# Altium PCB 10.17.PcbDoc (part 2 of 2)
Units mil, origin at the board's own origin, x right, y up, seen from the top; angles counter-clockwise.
Board outline 3750 x 1920 mil, 2 copper layers (Top Layer, Bottom Layer), stack 30.359 mil thick; 119 components, 118 nets, 550 pads, 365 vias.
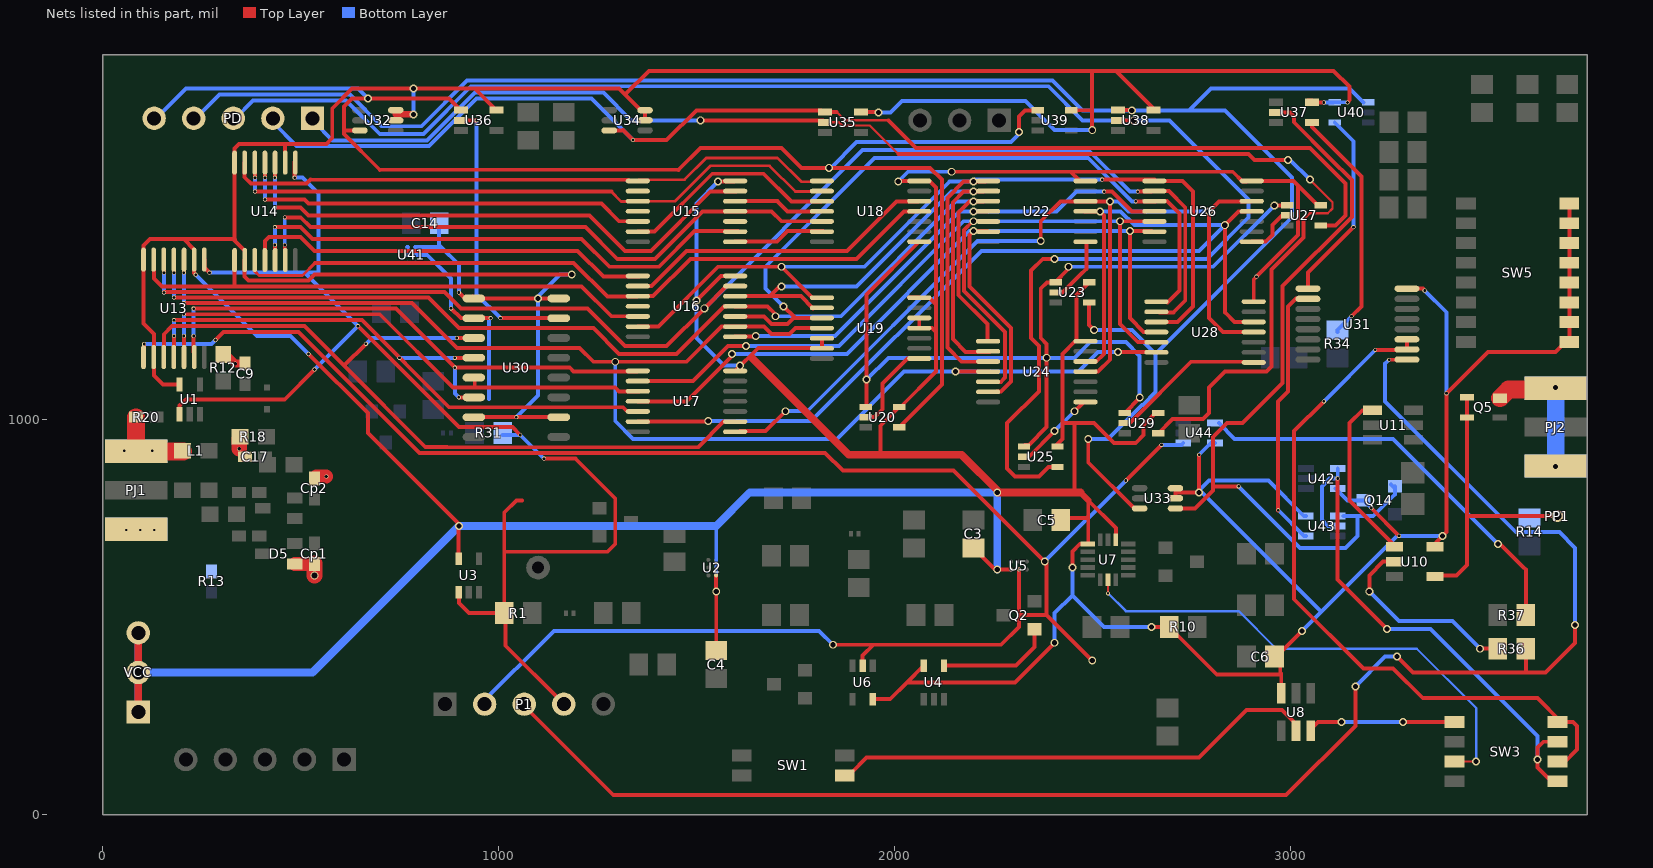
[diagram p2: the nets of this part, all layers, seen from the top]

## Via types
v1: diameter 20, hole 13, Top Layer to Bottom Layer, 179 vias
v2: diameter 10, hole 6.5, Top Layer to Bottom Layer, 137 vias
v3: diameter 10, hole 7, Top Layer to Bottom Layer, 28 vias
v4: diameter 10, hole 8, Top Layer to Bottom Layer, 10 vias
v5: diameter 10, hole 6, Top Layer to Bottom Layer, 7 vias
v6: diameter 8, hole 6, Top Layer to Bottom Layer, 2 vias
v7: diameter 20, hole 15, Top Layer to Bottom Layer, 1 vias
v8: diameter 10, hole 6.5, Top Layer to Bottom Layer, tented top, 1 vias

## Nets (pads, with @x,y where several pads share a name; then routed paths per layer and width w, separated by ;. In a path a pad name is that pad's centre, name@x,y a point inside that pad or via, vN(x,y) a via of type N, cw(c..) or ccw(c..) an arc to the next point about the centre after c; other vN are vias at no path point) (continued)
NetU10_1: U10.1 U11.1 | length 436.6
  Top Layer w10: U11.1@3208.43,1022.4 3182.4,1022.4 3150,990 3150,795 U10.1@3270,675
NetU19_8: U19.8 U20.2 | length 234.8
  Top Layer w10: U20.2@1927.68,1005 1950,1005 1970,1025 1970,1090 2033.23,1153.23 U19.8@2063.03,1153.23
NetU22_8: U22.8 U23.2 | length 167.2
  Top Layer w10: U23.2@2407.68,1320 2425,1320 2467.46,1362.46 2467.57,1362.46 2485,1379.89 U22.8@2485,1445
NetU24_8: U24.8 U25.2 | length 210.3
  Top Layer w10: U25.2@2327.68,905 2340,905 v1(2405,970) ; v1(2455,1020) U24.8@2475,1040
  Bottom Layer w10: v1(2405,970) v1(2455,1020) v1@2460,1025
NetU26_8: U26.8 U27.2 | length 119.3
  Top Layer w10: U26.8@2903.03,1448.23 2938.23,1448.23 2955,1465 2955,1490 U27.2@2980,1515
NetU28_8: U28.8 U29.2 | length 381.5
  Top Layer w10: U29.2@2582.68,990 2595,990 2750,1145 U28.8@2900,1145
NetU41_B2: U41.B2 U41.B3 | length 19.8
  Bottom Layer w10: U41.B2@770,1415 770.16,1415.16 U41.B3@770.16,1434.69
P1: U14.13 U15.1 U18.1 | length 1538
  Top Layer w7: U15.1@1330,1605 U15.1@1335,1600 ; U15.1@1351.97,1601.77 1355.2,1605 1470,1605 1525,1660 1705,1660 1765,1600 U18.1@1815,1600
  Top Layer w8: 525,1605 U15.1@1330,1605
  Top Layer w10: U14.13@358.82,1648.03 358.82,1611.18 375,1595 515,1595 525,1605
P1-: U15.2
P2: U14.12 U15.3 U18.2 | length 1557.3
  Top Layer w7: 1285,1575 1310,1550 U15.3@1350,1550 ; U15.3@1351.97,1550.59 1445.59,1550.59 1535,1640 1685,1640 1750,1575 U18.2@1810,1575
  Top Layer w10: v3(385,1575) 1285,1575 ; v3(385,1610) U14.12@385,1635
  Bottom Layer w10: v3(385,1575) v3(385,1610)
P2-: U15.4
P3: U14.11 U15.5 | length 1002.8
  Top Layer w10: v3(410,1555) 510,1555 520,1545 1260,1545 1305,1500 U15.5@1325,1500 ; v3(410,1610) U14.11@410,1620
  Bottom Layer w10: v3(410,1555) v3(410,1610)
P3-: U15.6 U18.3 | length 552.6
  Top Layer w10: U15.6@1351.97,1473.82 1393.82,1473.82 1540,1620 1670,1620 1740,1550 U18.3@1815,1550
P4: U14.10 U15.13 | length 1362.7
  Top Layer w10: v3(435,1535) 500,1535 520,1515 1230,1515 1320,1425 1385,1425 1535,1575 U15.13@1600,1575 ; v3(435,1610) U14.10@435,1625
  Bottom Layer w10: v3(435,1535) v3(435,1610)
P4-: U15.12 U18.4 | length 227.9
  Top Layer w10: U15.12@1598.03,1550.59 1705,1550.59 1705,1550 1730,1525 U18.4@1815,1525
P5: U14.6 U15.11 U18.5 | length 1561.8
  Top Layer w10: U14.6@460,1400 v3(460,1440) ; v3(460,1510) 500,1510 525,1485 1220,1485 1300,1405 1395,1405 1515,1525 U15.11@1598.03,1525 1690,1525 1715,1500 U18.5@1800,1500 ; U18.5@1816.97,1499.41 1824.41,1499.41 U18.5@1825,1500
  Bottom Layer w10: v3(460,1440) v3(460,1510)
P5-: U15.10
P6: U14.5 U15.9 | length 1328.7
  Top Layer w10: U14.5@435,1405 v3(435,1440) ; v3(435,1485) 500,1485 530,1455 1210,1455 1280,1385 1405,1385 1495,1475 U15.9@1605,1475
  Bottom Layer w10: v3(435,1440) v3(435,1485)
P6-: U15.8 U18.6 | length 236.6
  Top Layer w10: U15.8@1598.03,1448.23 1703.23,1448.23 1730,1475 1820,1475 1818.82,1473.82 U18.6@1816.97,1473.82
P7: U14.4 U16.1 | length 1038.6
  Top Layer w10: U14.4@410,1401.97 410,1450 420,1460 500,1460 535,1425 1200,1425 1265,1360 U16.1@1355,1360
P7-: U16.2 U18.12 | length 796.6
  Top Layer w10: U16.2@1351.97,1336.18 1386.18,1336.18 1475,1425 1880,1425 2005,1550 U18.12@2060,1550
P8: U14.3 U16.3 U18.11 | length 1843.7
  Top Layer w8: U14.3@384.41,1401.97 384.41,1373.59 395,1363 505,1363 537,1395
  Top Layer w10: 537,1395 585,1395 1190,1395 1275,1310 U16.3@1350,1310 ; U16.3@1351.97,1310.59 1390.59,1310.59 1485,1405 1905,1405 2025,1525 U18.11@2060,1525
P8-: U16.4
P9: U13.13 U14.1 U16.5 | length 1339.5
  Top Layer w10: U13.13@130,1395 130,1355 150,1335 1210,1335 1285,1260 U16.5@1325,1260 ; 333.23,1336.77 U14.1@333.23,1401.97
P9-: U16.6 U19.1 U22.1 U24.3 U26.1 U28.3 | length 2675.6
  Top Layer w10: U16.6@1351.97,1233.82 1403.82,1233.82 1555,1385 v1(1715,1385) U19.1@1790,1310 ; U24.3@2225,1145 2170,1145 2134,1181 2134,1559 2175,1600 U22.1@2230,1600 ; v2(2525,1605) 2656.97,1605 U26.1@2656.97,1601.77 2728.23,1601.77 2755,1575 2755,1285 2715,1245 U28.3@2660,1245
  Bottom Layer w10: v1(1715,1385) 1925,1385 2140,1600 v1(2200,1600) 2205,1605 v2(2525,1605)
P10: U13.12 U16.13 U26.2 U28.2 | length 3365.2
  Top Layer w10: v3@155,1321 864,1321 905,1280 1225,1280 1320,1185 1425,1185 v1(1520,1280) U16.13@1575,1335 ; v3(155,1370) U13.12@155,1400 ; v2(2615,1575) U26.2@2650,1575 ; U26.2@2656.97,1576.18 2693.82,1576.18 2735,1535 2735,1300 2705,1270 U28.2@2670,1270
  Bottom Layer w10: v3(155,1320) v3(155,1370) ; v1(1520,1280) 1920,1680 2490,1680 2595,1575 v2(2615,1575)
P10-: U16.12 U19.2 U22.2 U24.2 | length 1369.7
  Top Layer w10: U16.12@1598.03,1310.59 1685.59,1310.59 ; v1@1710,1335 1685.59,1310.59 ; v1@1713.82,1336.18 v1(1715,1335) ; U19.2@1795,1280 1764.41,1310.59 1685.59,1310.59 ; U22.2@2225,1575 2175,1575 2148,1548 2148,1202 2180,1170 U24.2@2240,1170
  Bottom Layer w10: v1(1715,1335) 1905,1335 2145,1575 v1(2200,1575)
P11: U13.11 U16.11 U22.3 U24.1 | length 2762.6
  Top Layer w10: v3(180,1307) 823,1307 900,1230 1240,1230 1305,1165 1450,1165 1570,1285 U16.11@1575,1285 ; v3(180,1370) U13.11@180,1408.03 ; U16.11@1598.03,1285 1680,1285 v1@1700,1265 ; v1@1699.41,1259.41 v1(1700,1260) ; U22.3@2225,1550 2190,1550 2162,1522 2162,1313 2235,1240 U24.1@2235,1200
  Bottom Layer w10: v3(180,1307) v3(180,1370) ; v1(1700,1260) 1865,1260 2155,1550 v1(2200,1550)
P11-: U16.10 U19.3 U26.3 U28.1 | length 1849.9
  Top Layer w10: U16.10@1598.03,1259.41 1670.59,1259.41 1690,1240 1730,1240 1747.5,1257.5 v1(1720,1285) ; 1745,1255 U19.3@1815,1255 ; v2(2610,1550) U26.3@2660,1550 ; U26.3@2656.97,1550.59 2689.41,1550.59 2720,1520 2720,1325 U28.1@2690,1295
  Bottom Layer w10: v1(1720,1285) 1675,1330 1675,1385 1950,1660 2490,1660 2600,1550 v2(2610,1550)
P12: U13.10 U16.9 U19.4 U24.4 U28.6 | length 3546.3
  Top Layer w10: v3(205,1293) 782,1293 895,1180 1205,1180 1240,1145 v1(1295,1145) 1475,1145 1563.82,1233.82 U16.9@1598.03,1233.82 1671.18,1233.82 1690,1215 1735,1215 1750,1230 U19.4@1815,1230 ; v3@205.59,1370.59 U13.10@205.59,1408.03 ; v1(2155,1120) U24.4@2236.97,1120 U24.4@2240,1120 ; v1(2565,1170) U28.6@2660,1170
  Bottom Layer w10: v3(205,1293) v3(205,1370) ; v1(1295,1145) 1295,995 1340,950 1855,950 2025,1120 v1(2155,1120) 2465,1120 2515,1170 v1(2565,1170)
P12-: U16.8 U22.4 U26.4 | length 1243.9
  Top Layer w10: U16.8@1598.03,1208.23 v1@1650,1208.23 ; v1(2200,1525) U22.4@2235,1525 ; v8(2530,1575) 2550,1575 2600,1525 U26.4@2635,1525
  Bottom Layer w10: v1(1650,1210) 1850,1210 2165,1525 v1(2200,1525) 2410,1525 2460,1575 v8(2530,1575)
P13: U13.6 U17.1 U30.6 | length 1411.7
  Top Layer w10: U13.6@230,1170 v3(230,1210) ; v3(230,1279) 741,1279 v2(890,1130) 1180,1130 1190,1120 U17.1@1350,1120 ; v2(900,1055) U30.6@937.72,1055
  Bottom Layer w10: v3(230,1210) v3(230,1279) ; v2(890,1130) 890,1065 v2(900,1055)
P13-: U17.2 U22.5 U24.5 U26.5 U28.5 | length 2365.5
  Top Layer w10: U17.2@1351.97,1096.18 1491.18,1096.18 1580,1185 v1@1620,1185 ; U24.5@2236.97,1094.41 2269.41,1094.41 2280,1105 2280,1220 2176,1324 2176,1477.87 2198.13,1500 U22.5@2240,1500 ; U28.5@2655,1195 2615,1195 2570,1240 v1(2570,1500) U26.5@2655,1500
  Bottom Layer w10: v1(1625,1185) 1860,1185 2175,1500 v1(2570,1500)
  other v1: 2200,1500
P14: U13.5 U17.3 U30.5 | length 1325.8
  Top Layer w10: 205,1190 v3(205,1210) ; v3(205,1265) 700,1265 885,1080 940,1080 ; U30.5@940,1100 940,1080 ; U17.3@1355,1070 1305,1070 1295,1080 940,1080
  Bottom Layer w10: v3(205,1210) v3(205,1265)
P14-: U17.4 U22.6 U24.6 U26.6 U28.4 | length 2276.6
  Top Layer w10: U17.4@1351.97,1045 1475,1045 1590,1160 v1(1590,1165) ; U22.6@2235,1475 v1(2200,1475) 2190,1465 2190,1335 2295,1230 2295,1095 2270,1070 U24.6@2260,1070 ; U28.4@2650,1220 2630,1220 2595,1255 v1(2595,1475) U26.6@2650,1475
  Bottom Layer w10: v1(1590,1165) 1880,1165 2190,1475 v1(2595,1475)
P15: U13.4 U17.5 U30.4 | length 1510.3
  Top Layer w10: U13.4@180,1175 v3(180,1210) ; v3(180,1250) 655,1250 875,1030 1315,1030 U17.5@1325,1020 ; v2(890,1155) U30.4@937.72,1155 U30.4@945,1155
  Bottom Layer w10: v3(180,1210) v3(180,1250) ; v2(750,1155) 800,1155 v2(890,1155)
P15-: U17.6 U22.11 U24.12 U26.11 U28.12 | length 2826.1
  Top Layer w10: U17.6@1351.97,993.82 1526.18,993.82 v1(1530,995) ; U22.11@2480,1525 U22.11@2483.03,1525 v1(2520,1525) 2530,1515 2530,1165 U24.12@2510,1145 ; U28.12@2900,1245 2860,1245 2835,1270 2835,1495 2840,1495 2870,1525 U26.11@2900,1525
  Bottom Layer w10: v1(1530,995) 1733.13,995 ; 1735,995 1790,995 2220,1425 2770,1425 v1(2835,1490) 2606.87,1490 2571.87,1525 v1(2520,1525)
P16: U13.3 U17.9 U30.3 | length 2004.1
  Top Layer w10: U13.3@154.41,1171.97 154.41,1214.41 175,1235 510,1235 610,1135 ; v2(665,1190) 610,1135 ; 870,929 1505,929 ; 870,930 815,930 610,1135 ; v2(895,1205) U30.3@937.72,1205 ; 1505,930 1568.82,993.82 U17.9@1598.03,993.82
  Bottom Layer w10: v2(665,1190) 680,1205 v2(895,1205)
P16-: U17.8 U22.12 U24.11 U26.12 U28.11 | length 2428.8
  Top Layer w10: U17.8@1610,970 1675,970 v1(1725,1020) v1@1727.64,1020 ; v1(2370,1450) 2370,1500 2420,1550 v1(2545,1550) 2545,1150 2515,1120 U24.11@2510,1120 ; U26.12@2900,1550 2820,1550 v1(2795,1525) 2795,1255 2830,1220 U28.11@2908.03,1220 U28.11@2910,1220
  Bottom Layer w10: v1(1725,1020) 1780,1020 2210,1450 v1@2369,1450 ; v1(2545,1550) 2566.67,1550 2591.67,1525 v1(2795,1525)
PD: U18.8 U20.1 U23.1 U25.1 U27.1 U29.1 | length 2521.8
  Top Layer w10: U20.1@1930,1030 v1(1930,1100) 1930,1315.2 U18.8@2063.03,1448.23 ; U25.1@2330,935 2340,935 2385,980 v1(2385,1155) 2385,1190 2370,1205 2370,1330 2385.59,1345.59 U23.1@2405.59,1345.59 ; U23.1@2407.68,1345.59 U23.1@2405.59,1345.59 ; v1(2440,1385) 2440,1380 U23.1@2405.59,1345.59 ; U29.1@2582.68,1015.59 v1@2620,1052.91 ; v1(2960,1540) U27.1@2995,1540
  Bottom Layer w10: v1(1930,1100) 1985,1155 2455,1155 2495,1195 2585,1195 2620,1160 v1(2620,1055) ; v1(2440,1385) 2805,1385 v1(2960,1540)
PD1: PD.5 U20.4 U32.3 U36.1 U39.1 | length 3893.5
  Top Layer w8: 700,1630 1455,1630
  Top Layer w10: U32.3@649.72,1729.41 614.41,1729.41 610,1725 ; 700,1630 610,1720 610,1725 ; U36.1@905,1780 875,1810 v1(670,1810) 630,1810 610,1790 610,1725 ; 1455,1630 1510,1685 1715,1685 1765,1635 2090,1635 2120,1605 2120,1087.09 U20.4@2012.32,979.41 ; v1(2315,1725) 2315,1765 2330,1780 U39.1@2365,1780
  Bottom Layer w10: PD.5@135,1760 210,1835 645,1835 v1(670,1810) ; v1(1835,1635) 1840,1635 1905,1700 2295,1700 2315,1720 v1(2315,1725)
PD2: PD.4 U23.4 U33.3 U38.1 U40.1 | length 4877.8
  Top Layer w10: v1(2490,950) 2490,890 U33.3@2605,775 ; U23.4@2492.32,1294.41 2492.32,1237.68 v1(2505,1225) ; U38.1@2564.72,1780.59 2599.41,1780.59 v1(2600,1780)
  Bottom Layer w10: PD.4@230,1755 295,1820 625,1820 705,1740 805,1740 920,1855 2400,1855 2475,1780 v1(2600,1780) 2745,1780 ; v1(2490,950) 2540,950 2626,1036 2627.87,1036 2660,1068.13 2660,1165 ; v1(2505,1225) 2600,1225 2660,1165 ; U40.1@3185,1800 3150,1835 2800,1835 2745,1780 ; 2660,1165 3005,1510 3005,1610 2835,1780 2745,1780
PD3: PD.3 U25.4 U38.2 | length 4177.8
  Top Layer w10: v1(2405,1405) 2375,1405 2345,1375 2345,1205 2365,1185 2365,1070 2285,990 2285,875 2305,855 2365,855 2389.41,879.41 U25.4@2412.32,879.41 ; U38.2@2564.72,1755 v1(2605,1755)
  Bottom Layer w10: PD.3@330,1755 PD.3@335,1760 ; PD.3@335,1750 PD.3@335,1760 ; v1(2405,1405) 2790,1405 2895,1510 2895,1555 2695,1755 v1(2605,1755) 2475,1755 2389,1841 931,1841 810,1720 700,1720 615,1805 380,1805 PD.3@335,1760
PD4: PD.2 U27.4 U34.3 U35.1 | length 3155.8
  Top Layer w6: 1854.41,1775.59 1875,1755 1985,1755
  Top Layer w10: U34.3@1279.72,1729.41 1315.59,1729.41 ; 1315,1730 1315.59,1729.41 ; U35.1@1820,1775 1815,1780 1500,1780 1425,1705 v4(1340,1705) 1315.59,1729.41 ; U35.1@1824.72,1775.59 1854.41,1775.59 ; 1985,1755 2055,1685 3050,1685 3140,1595 3140,1515 3114.41,1489.41 U27.4@3077.32,1489.41
  Bottom Layer w10: PD.2@430,1750 490,1690 825,1690 945,1810 1235,1810 v4(1340,1705)
PD5: PD.1 U29.4 U35.2 | length 3649.6
  Top Layer w6: U35.2@1825,1750 1860,1750 1868,1742 1938,1742 2010,1670 ; 3034,1504 3050,1520 3095,1520 3107,1532 3107,1548 v1(3050,1605)
  Top Layer w10: v1@1515,1755 1820,1755 U35.2@1825,1750 ; 2010,1670 2895,1670 2910,1655 v1(2995,1655) ; U29.4@2667.32,964.41 2702.91,1000 2780,1000 2795,1015 2795,1080 2835,1120 2940,1120 2953,1133 2953,1378.2 3034,1459.2 3034,1504
  Bottom Layer w10: PD.1@535,1750 581,1704 819.2,1704 940.2,1825 1265,1825 1335,1755 v1(1510,1755) ; v1(2995,1655) 3000,1655 v1(3050,1605)
PIE: P1.4 R1.1 R31.1 U1.1 U3.1 U13.8 U14.8 | length 3399.7
  Top Layer w10: U1.1@194.41,1012.6 194.41,1034.41 210,1050 460,1050 v4(535,1125) ; U13.8@256.77,1403.03 256.77,1383.23 v2(270,1370) ; v2(485,1610) U14.8@485,1650 ; v2(645,1235) 900,980 900,979.69 1035.32,979.69 v2(1055,960) ; U3.1@900,560 900,535 925,510 1014.41,510 1014.41,495.59 1017.5,492.5 1017.5,427.5 P1.4@1157.5,287.5 ; R1.1@1014.57,510 1014.57,665 ; 1060,795 1045,795 1014.57,764.57 1014.57,665 ; v2(1115,900) 1195,900 1295,800 1295,685 1275,665 1014.57,665
  Bottom Layer w10: v2(270,1370) 510,1370 ; v2(485,1610) 505,1610 545,1570 545,1370 510,1370 ; v4(535,1125) v2(645,1235) 510,1370 ; R31.1@1010,960 v2(1055,960) v2(1115,900)
PIE_Delayed: U30.2 U41.A2 | length 506
  Top Layer w10: v2(880,1280) 905,1255 U30.2@937.72,1255 v2(980,1255)
  Bottom Layer w10: U41.A2@789.84,1415 820,1415 880,1355 v2(880,1280) ; 976,1051 976,1251 v2(980,1255)
Q2_CONTROL: Q2.1 U4.4 | length 293.5
  Top Layer w10: U4.4@2125.59,377.32 2307.32,377.32 2354.37,424.37 Q2.1@2354.37,469.57
RCO: U30.15 U36.2 | length 707.1
  Top Layer w10: U36.2@910,1755 v2(945,1755) ; v2(1005,1255) U30.15@1152.28,1255
  Bottom Layer w10: v2(945,1755) 945,1315 v2(1005,1255)
RXGND: C9.2 C17.2 Cp1.2 Cp2.2 D5.1 L1.1 PJ1.2 R12.1 R13.2 R18.2 R20.2 | length 442.7
  Top Layer w8: v5(130,720) PJ1.2@147,703
  Top Layer w20: R12.1@305,1163.46 311.54,1163.46 v4@334.41,1140.59 ; v4(335,1140) v4@334.41,1140.59 ; C9.2@360,1140.59 v4@334.41,1140.59
  Top Layer w35: D5.1@485.35,634.41 Cp1.2@535,634.41 ; Cp2.2@540,855 v4(565,855)
  Top Layer w35.43: PJ1.2@70,918.43 PJ1.2@85,918.43
  Top Layer w40: PJ1.2@84.41,920.59 PJ1.2@85,920 ; v4(345,925) R18.2@345,950 ; v7(535,605) Cp1.2@535,634.41 Cp1.2@535,635
  Top Layer w45: PJ1.2@84.41,920.59 R20.2@84.41,1005 ; PJ1.2@85,918.43 L1.1@203.43,918.43
  Bottom Layer w40: PJ1.2@65,721.57 PJ1.2@70,721.57
  other v5: 60,720 95,720 55,920 125,920
SCLK: SW3.1 SW3.3 U42.4 U43.2 | length 1334.7
  Top Layer w10: 3120,595 3120,595.2 ; v2(3120,850) 3120,595.2 ; v1(3245,470) 3245,470.2 3120,595.2 ; SW3.1@3660,85 3625,120 3625,170 3640,185 SW3.3@3680,185
  Bottom Layer w10: U43.2@3105,730 3095,730 3080,745 3080,830 3100,850 v2(3120,850) 3120.28,850.28 U42.4@3120.28,875.59 ; v1(3245,470) 3355,470 3625,200 v1(3625,140)
SCLK_EN: R34.1 U37.4 | length 611.3
  Top Layer w10: U37.4@3055,1745 3055,1737.69 3180,1612.69 3180,1285 v2(3155,1260) ; 3055.28,1739.72 U37.4@3055.28,1749.41
  Bottom Layer w10: R34.1@3120,1220 3120,1225 v2(3155,1260)
SDATA: R37.1 U44.4 | length 1038.3
  Top Layer w10: v1@3530.2,685 3590.1,625.1 ; 3590,625 3595.43,619.57 R37.1@3595.43,505
  Bottom Layer w10: U44.4@2820,990 2860,950 3260,950 v1(3525,685)
SENSOROUT: SW3.2 SW3.4 U31.10 U31.11 | length 1763
  Top Layer w10: v2(3085,1045) 3010,970 3010,545 3185,370 3260,370 3335,295 3625,295 SW3.4@3685,235 ; v2(3215,1175) U31.10@3275,1175 ; U31.10@3295,1176.02 U31.11@3295,1200 ; SW3.2@3690,130 3725,165 3725,225 3715,235 SW3.4@3685,235 ; SW3.4@3690,230 SW3.4@3685,235
  Bottom Layer w10: v2(3085,1045) v2(3215,1175)
SENSOROUT_ADXL: SW3.7 U7.7 | length 1280.1
  Top Layer w6: v5(2540,560) U7.7@2540,594.8 U7.7@2540,595 ; SW3.7@3410,135 3419.37,135 v1(3470,135)
  Bottom Layer w6: v5(2540,560) 2585,515 2870,515 2965,420 3320,420 3470,270 v1(3470,135)
SENSOROUT_TEMP: SW3.5 U8.6 | length 382.8
  Top Layer w10: U8.6@3050,215 U8.6@3052.4,217.4 ; U8.6@3052.4,205 U8.6@3052.4,212.76 U8.6@3052.4,217.4 ; v1(3130,235) 3070,235 U8.6@3052.4,217.4 ; v1(3285,235) 3405,235 SW3.5@3410,240
  Bottom Layer w10: v1(3130,235) v1(3285,235)
SH/L\D\: U31.1 U40.4 | length 487.1
  Top Layer w10: U31.1@3045,1329.57 3045,1370 v2(3160,1485)
  Bottom Layer w10: U40.4@3112.68,1749.41 3160,1702.09 v2(3160,1485)
SHIFT-OUT: P1.3 R36.2 U31.9 | length 4082
  Top Layer w10: P1.3@1055,285 1290,50 2990,50 3165,225 v1(3165,325) ; v2(3250,1150) U31.9@3275.85,1150 ; v1(3270,400) 3310,360 3595,360 ; R36.2@3595.43,420 3595.43,360.43 3595,360 ; v1(3720,480) 3720,435 3645,360 3595,360
  Bottom Layer w10: v1(3165,325) 3240,400 v1(3270,400) ; v2(3250,1150) 3240,1140 3240,1045 3570,715 3680,715 3720,675 v1(3720,480)
SPI_DATA: P1.2 U5.A2 U6.2 U13.1 U44.1 | length 5086
  Top Layer w10: U13.1@105,1165 v3(105,1190) ; v3(285,1200) 305,1220 495,1220 800,915 1825,915 1870,870 2150,870 v1(2380,640) 2385,635 2385,505 ; v1(1845,430) 1947,430 ; U6.2@1920,377.32 1920,403 1947,430 ; U5.A2@2315,620.16 2315,505 ; v1(2500,390) 2385,505 ; v2(2585,845) v2(2675,935) ; 1947,430 2270,430 2315,475 2315,505 ; 2315,505 2385,505
  Bottom Layer w10: v3(105,1190) 275,1190 v3(285,1200) ; P1.2@947.5,272.5 1140,465 1810,465 v1(1845,430) ; v1(2380,640) v2(2585,845) ; v2(2675,935) 2725,935 U44.1@2730,940
TEMP_CS: SW1.4 U8.5 | length 1205.8
  Top Layer w10: SW1.4@1890,105 1930,145 2770,145 2800,175 2805,180 2890,265 2980,265 U8.5@3015,230
TX: PP1.0 Q5.3 U10.4 | length 753.2
  Top Layer w10: U10.4@3357.32,605 3420,605 3446.98,631.98 3446.98,758.02 ; Q5.3@3446.98,1055.04 Q5.3@3446.98,1003.86 3446.98,758.02 ; PP1.0@3675,755 3450,755 3446.98,758.02
TX_CLK: U31.2 U43.4 | length 656.1
  Top Layer w10: v2@2969.57,769.57 2969.57,1044.57 2995,1070 2995,1285 3015,1305 U31.2@3020,1305
  Bottom Layer w10: v2(2970,770) 3035.59,704.41 U43.4@3039.72,704.41
TX_CLK_EN: Q14.1 U33.4 U37.2 U43.1 | length 2004
  Top Layer w10: U33.4@2710.28,774.41 2759.41,774.41 2805,820 2805,955 2840,990 2880,990 2981,1091 2981,1336 3156,1511 3156,1604 3100,1660 3100,1660.11 3010,1750.11 3010,1765 3000,1775 U37.2@2964.72,1775 ; 2810,830 v2(2870,830)
  Bottom Layer w10: v2(2870,830) 3025,675 3140,675 3170,705 3170,755 ; U43.1@3135,755 3170,755 ; Q14.1@3255,835 Q14.1@3260,830 ; Q14.1@3264.37,830.43 3264.37,809.37 3210,755 3170,755
TX_CTRL: R36.1 U10.2 | length 504.6
  Top Layer w10: v1(3200,565) 3200,605 3235,640 U10.2@3265,640 ; v1(3480,420) R36.1@3525,420
  Bottom Layer w10: v1(3200,565) 3275,490 3410,490 v1(3480,420)
TXGND: PJ2.2 Q5.1 R14.1 | length 346
  Top Layer w45: Q5.1@3530,1053 3552,1075 PJ2.2@3670,1075
  Bottom Layer w45: PJ2.2@3670.91,881.5 PJ2.2@3670.91,1078.35
  other v1: 3670,880 3670,1080
VCC: C3.2 C4.2 C5.2 C6.2 C14.2 Q14.3 R10.1 SW5.9 SW5.10 SW5.11 SW5.12 SW5.13 SW5.14 SW5.15 SW5.16 U1.5 U2.A3 U3.5 U4.5 U5.A3 U6.5 U7.1 U7.14 U8.3 U10.5 U13.2 U13.9 U13.14 U14.2 U14.9 U14.14 U15.14 U16.14 U17.14 U18.14 U19.5 U19.6 U19.11 U19.12 U19.14 U20.5 U22.14 U23.5 U24.14 U25.5 U26.14 U27.5 U28.14 U29.5 U30.1 U30.7 U30.10 U30.16 U31.16 U32.5 U32.6 U33.5 U33.6 U34.5 U34.6 U35.5 U36.5 U37.5 U38.5 U39.5 U40.5 U41.A3 U42.5 U43.5 U44.5 VCC.1 VCC.2 VCC.3 | length 22216.4
  Top Layer w8: U39.5@2447.32,1780.59 2494.41,1780.59 ; U38.5@2665,1780 U38.5@2665.91,1779.09
  Top Layer w10: U13.2@130,1170 130,1110 152.6,1087.4 U1.5@194.41,1087.4 ; U13.2@130,1180 130,1215 103.23,1241.77 U13.14@103.23,1403.03 103.23,1438.23 120,1455 205,1455 ; U13.9@230,1430 205,1455 ; U13.9@231.18,1403.03 231.18,1368.82 v3(235,1365) ; 335,1453.54 333.23,1451.77 ; U14.2@358.82,1401.97 358.82,1360.18 369,1350 520,1350 535,1365 v1(1185,1365) ; U14.2@360,1425 333.23,1451.77 ; U14.9@461.18,1648.03 461.18,1693.82 460,1695 ; v4(520,1165) 670,1015 670,965 v1@900,735 ; U32.5@740.28,1755.28 740.28,1770 U32.6@740.28,1780.59 ; U3.5@899.41,647.32 v1@899.41,735 ; v2(900,1320) 915,1305 U30.1@937.72,1305 ; U30.1@935,1310 940,1305 v1(1100,1305) U30.16@1150,1305 ; U30.7@937.72,1005 v2(1045,1005) U30.10@1152.28,1005 U30.10@1160,1005 ; U36.5@990,1785 940,1835 ; U34.6@1355,1785 1320,1820 ; U34.5@1370,1755 1370.28,1755.28 U34.6@1370.28,1780.59 ; v1(1500,1300) 1561.77,1361.77 U16.14@1598.03,1361.77 ; v1@1550,565.16 U2.A3@1550,605.31 ; C4.2@1550.16,415.43 v1(1550.16,565) ; v1(1555,1600) U15.14@1595,1600 ; U17.14@1598.03,1121.77 1656.26,1180 1815,1180 1816.97,1181.97 U19.5@1816.97,1204.41 ; U35.5@1915.28,1775.59 v1@1960,1775.59 ; U6.5@1945.59,292.68 1989.76,292.68 2032.09,335 ; 1965,910 1965,983.27 U20.5@2012.32,1030.59 ; v1@2011.77,1601.77 U18.14@2063.03,1601.77 U18.14@2081.77,1601.77 ; U20.5@2015,1030 2105,1120 2105,1220 ; U19.14@2036.77,1306.77 U19.14@2063.03,1306.77 ; U19.11@2063.03,1230 U19.12@2063.03,1255.59 ; U4.5@2074.41,377.32 2032.09,335 ; U19.11@2090,1230 2095,1230 2105,1220 ; U19.14@2090,1305 2105,1290 ; U18.14@2090,1600 2105,1585 2105,1290 ; v1(2145,1625) 2445,1625 ; C3.2@2200,674.57 2254.41,620.16 U5.A3@2295.31,620.16 ; v1@2404.57,435 2404.57,434.57 2305,335 2032.09,335 ; U25.5@2410,935 2425,950 2425,990 ; C5.2@2415.43,760 2425.43,750 2485,750 2490,755 ; U39.5@2445,1780 U39.5@2450,1780 ; v1(2450,625) 2450,665.93 2468.44,684.37 U7.1@2488.82,684.37 ; 2455,820 2455,990 ; U22.14@2465,1605 2445,1625 ; U24.14@2483.03,1196.77 U24.14@2460,1196.77 ; 2490,690.41 2490,755 ; U23.5@2492.32,1345.59 2460,1313.27 U24.14@2460,1196.77 ; v1(2500,1730) 2500,1880 ; U7.14@2559.69,695.2 2559.69,725.31 2490,795 2490,755 ; v1(2650,475) R10.1@2694.57,475 2814.57,355 2975,355 ; U29.5@2660,1015 2630,985 2630,960 2610,940 2555,940 2505,990 2455,990 ; U38.5@2660,1780 2560,1880 ; U33.5@2710.28,800.28 2710,800.55 2710,815 v1@2765,815 ; v1(2770,815) v2(2770,910) ; U26.14@2890,1600 2880,1600 2855,1625 2445,1625 ; U26.14@2903.03,1601.77 3008.23,1601.77 3020,1590 ; U28.14@2908.03,1296.77 2908.03,1353.03 v2(2915,1360) 3020,1465 3020,1590 ; C6.2@2960,400 2965,400 v1(3030,465) ; 2975,360 C6.2@2975,400 ; U8.3@2977.6,307.24 2977.6,357.4 ; U37.5@3045,1805 U37.5@3055,1805 ; U37.5@3055,1800 v2(3085,1800) ; U27.5@3070,1540 3020,1590 ; v4@3147.19,1802.81 3150,1805.62 3150,1840 3110,1880 2560,1880 ; v2(3205,775) v2(3275,705) ; U31.16@3295,1329.57 3335.43,1329.57 v2(3340,1325) ; U10.5@3370,680 3370,690 v1(3385,705) ; v1@3390,710 3395,715 v2(3395,1065) 3500,1170 3670,1170 3705.63,1205.63 3705.63,1295 3705.63,1445 SW5.16@3705.63,1545 ; 205,1455 330,1455 333.23,1451.77 ; 333.23,1451.77 U14.14@333.23,1648.03 333.23,1683.23 345,1695 460,1695 ; 460,1695 565,1695 580,1710 580,1785 630,1835 v1(785,1835) 940,1835 ; 940,1835 1305,1835 1320,1820 ; 1320,1820 1380,1880 2350,1880 2500,1880 ; 2105,1220 2105,1290 ; 2425,990 2455,990 ; 2425,990 2425,1165 2456.77,1196.77 U24.14@2460,1196.77 ; 2500,1880 2560,1880
  Top Layer w16: 740.28,1770 v1(785,1770) ; 2470,815 2490,795
  Top Layer w20: VCC.1@90,260 VCC.2@90,360 VCC.3@90,460 ; 1640,1155 1885,910 1965,910 2170,910 2265,815 2470,815
  Bottom Layer w8: U40.5@3112.68,1800.59 3144.41,1800.59 v4(3145,1800)
  Bottom Layer w10: v3(235,1365) 390,1210 475,1210 v4(520,1165) ; v1@785,1775 v1(785,1835) ; U41.A3@790,1435 855,1435 ; C14.2@850,1485 850,1440 855,1435 ; v2(900,1320) 900,1390 855,1435 ; v2(1045,1005) 1100,1060 v1(1100,1305) 1100,1310 1155,1365 v1(1185,1365) ; v1(1550.16,565) 1550.16,730.16 ; v1(1555,1600) 1500,1545 v1(1500,1300) 1500,1205 1570,1135 v1(1610,1135) ; v1(1960,1775) 1990.51,1775 2019.04,1803.53 2331.47,1803.53 2405,1730 v1(2500,1730) ; v1(2010,1600) 2035,1625 v1(2145,1625) ; v1(2405,435) 2405,510 2450,555 ; v1(2450,625) 2450,555 ; v1(2650,475) 2530,475 2450,555 ; v1(2770,815) 2777.14,815 3077.14,515 3080,515 ; v1@2770,820 2795,845 2945,845 3034.41,755.59 U43.5@3039.72,755.59 ; v2(2770,910) 2799.41,939.41 U44.5@2810.28,939.41 ; 3037.5,472.5 3080,515 ; v2(3085,1800) U40.5@3110,1800 ; U42.5@3115,825 3145,795 Q14.3@3185.63,795 ; Q14.3@3190,790 v2(3205,775) ; v2(3340,1325) 3395,1270 v2(3395,1065) ; v1(3385,705) v2(3275,705) 3270,705 3080,515
  Bottom Layer w20: VCC.1@90,275 VCC.2@90,360 ; VCC.3@90,460 VCC.2@90,360 ; v1@2255,815 1635,815 1550.16,730.16 1550,730 v1(900,730) 530,360 VCC.2@90,360 ; v1(2260,620) v1(2260,815)
pads on no net: SW5.1 U7.2 U7.3 U7.5 U7.9 U7.10 U7.15 U11.5 U17.10 U17.11 U17.12 U17.13 U18.9 U18.10 U18.13 U19.9 U19.10 U19.13 U22.9 U22.10 U22.13 U24.9 U24.10 U24.13 U26.9 U26.10 U26.13 U28.9 U28.10 U28.13 U30.11 U30.12 U30.13 U30.14 U31.7
copper on no net: | length 511.6
  Top Layer w10: 3310,985 3355,985 3355,825 3260,825 3260,985 3311.57,985
  other v1: 990,1685

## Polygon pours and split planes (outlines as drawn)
GND on Bottom Layer "Bottom Layer-GND" (solid, remove dead copper, pour order 16): 0,580 0,0 3750,0 3750,720 3565,720 3445,840 3445,1130 3750,1130 3750,1920 0,1920 0,1160 505,1160 640,1025 640,580
TXGND on Bottom Layer "Bottom Layer-TXGND" (solid, remove dead copper, pour order 12): 3750,1120 3475,1120 3475,830 3575,730 3750,730
RXGND on Bottom Layer "Bottom Layer-RXGND" (solid, remove dead copper, pour order 10): 0,1150 495,1150 620,1025 620,590 0,590
GND on Top Layer "Top Layer-GND" (solid, remove dead copper, pour order 18): 0,1160 505,1160 640,1025 640,580 0,580 0,0 3750,0 3750,720 3570,720 3450,840 3450,1125 3445,1130 3750,1130 3750,1920 0,1920

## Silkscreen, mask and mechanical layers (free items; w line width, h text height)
Top Overlay:
  region: 2955,590 2950,590 2950,580 2955,580
  rectangle: 1170,470 1175,480
  rectangle: 1895,735 1900,745
  lines w5: 1155,475 1200,475 ; 1183,465 1183,485 ; 1880,740 1925,740 ; 1908,730 1908,750 ; 2925,585 2970,585 ; 2942,575 2942,595 ; 1170,465 1180,475 1170,485 1170,465 ; 1895,730 1895,750 1905,740 1895,730 ; 2945,585 2955,575 2955,595 2945,585
  text "1  2  3  4  5" at 120,1825 h34
  text "VCC" at 730,865 h30 r90
  text "TXShift" at 1070,225 h30 r270
  text "DATA" at 930,220 h30 r270
  text "SPI" at 965,220 h30 r270
  text "out" at 1030,220 h30 r270
  text "_raw" at 1240,220 h30 r270
  text "_raw" at 1240,220 h30 r270
  text "Data" at 1275,220 h30 r270
  text "Data" at 1275,220 h30 r270
  text "CLK" at 835,215 h30 r270
  text "PIE" at 1145,215 h30 r270
  text "TEMP" at 3385,170 h30 r90
  text "ADXL" at 1910,140 h20
  text "TEMP" at 1910,90 h20
  text "ADXL" at 3385,35 h30 r90
Bottom Overlay:
  region: 880,940 875,940 875,930 880,930
  lines w5: 850,935 895,935 ; 867,925 867,945 ; 870,935 880,925 880,945 870,935
Top Solder:
  rectangle: 770,1510 795,1520
  rectangle: 770,1480 795,1490
  rectangle: 770,1420 795,1430
  rectangle: 770,1450 795,1460
  rectangle: 770,1570 795,1580
  rectangle: 770,1540 795,1550
  rectangle: 770,1600 795,1610
  rectangle: 770,1600 795,1610
  rectangle: 770,1390 795,1400
  rectangle: 770,1330 795,1340
  rectangle: 730,1316 755,1326
  rectangle: 690,1302 715,1312
  rectangle: 565,1260 590,1270
  rectangle: 605,1274 630,1284
  rectangle: 645,1288 670,1298
  rectangle: 480,1230 505,1240
  rectangle: 520,1245 545,1255
Mechanical 1:
  the board outline again, w10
